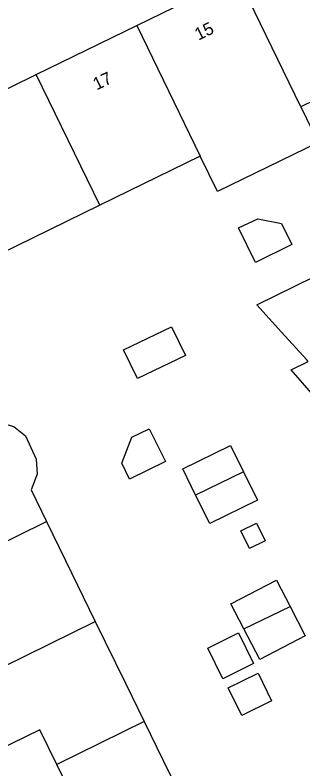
# Model space of a CAD drawing. Extents: x 160457 to 162082, y 388340 to 389736.
# Drawn here: x 160790 to 160813.2, y 388775.3 to 388835.9 of the extents above; entities that cross this region are included whole.
import ezdxf

# ---------------------------------------------------------------- set-up
doc = ezdxf.new("R2010")
doc.units = 0
doc.layers.add('IMGEO_Pand', color=7, linetype='Continuous')
doc.layers.add('IMGEO_Pand_nummerreeks', color=7, linetype='Continuous')

msp = doc.modelspace()

# ---------------------------------------------------------------- linework, layer by layer
at = {"layer": 'IMGEO_Pand'}
for points in [[(160807.926, 388838.972), (160816.305, 388843.064), (160816.478, 388842.742), (160816.37, 388842.689), (160821.325, 388832.529), (160813.027, 388828.476)], [(160799.832, 388835.019), (160807.926, 388838.972)], [(160813.027, 388828.476), (160807.926, 388838.972)], [(160791.746, 388831.069), (160799.832, 388835.019)], [(160799.832, 388835.019), (160804.945, 388824.528)], [(160783.66, 388827.12), (160791.746, 388831.069)], [(160796.865, 388820.581), (160791.746, 388831.069)], [(160813.027, 388828.476), (160814.416, 388825.619), (160806.337, 388821.673), (160804.945, 388824.528)], [(160804.945, 388824.528), (160796.865, 388820.581)], [(160796.865, 388820.581), (160788.782, 388816.633)], [(160809.381, 388815.983), (160808.031, 388818.746), (160809.564, 388819.495), (160811.484, 388819.096), (160812.307, 388817.412), (160809.381, 388815.983)], [(160813.637, 388808.009), (160813.488, 388808.173), (160811.49, 388810.37), (160809.493, 388812.567), (160814.137, 388814.839), (160818.628, 388817.036), (160821.252, 388811.672)], [(160799.882, 388806.648), (160798.774, 388808.962), (160802.639, 388810.812), (160803.746, 388808.498), (160799.882, 388806.648)], [(160816.137, 388802.883), (160815.992, 388803.05), (160814.791, 388804.429), (160812.251, 388807.343), (160813.637, 388808.009)], [(160777.041, 388797.369), (160776.904, 388797.662), (160781.436, 388799.775), (160786.382, 388802.287), (160788.669, 388803.147), (160789.935, 388802.8), (160790.875, 388802.036), (160791.746, 388800.169), (160791.808, 388798.959), (160791.328, 388797.695), (160792.571, 388795.154)], [(160799.261, 388798.561), (160798.632, 388799.84), (160799.447, 388801.927), (160800.842, 388802.614), (160802.14, 388799.977), (160799.261, 388798.561)], [(160804.57, 388797.282), (160803.528, 388799.399), (160807.372, 388801.279), (160808.422, 388799.147)], [(160808.422, 388799.147), (160804.57, 388797.282)], [(160808.422, 388799.147), (160809.543, 388796.872), (160805.699, 388794.992), (160804.57, 388797.282)], [(160782.547, 388790.23), (160785.541, 388791.701), (160792.571, 388795.154)], [(160792.571, 388795.154), (160794.101, 388792.028), (160796.497, 388787.131)], [(160808.207, 388794.418), (160809.479, 388795.039), (160810.173, 388793.62), (160808.901, 388792.999), (160808.207, 388794.418)], [(160808.457, 388786.533), (160807.413, 388788.546), (160811.079, 388790.447), (160812.178, 388788.328)], [(160812.178, 388788.328), (160813.391, 388785.988), (160809.725, 388784.087), (160808.457, 388786.533)], [(160808.457, 388786.533), (160812.178, 388788.328)], [(160785.414, 388781.697), (160796.497, 388787.131)], [(160796.497, 388787.131), (160798.923, 388782.173), (160800.43, 388779.094)], [(160805.55, 388784.997), (160808.025, 388786.208), (160809.232, 388783.742), (160806.757, 388782.531), (160805.55, 388784.997)], [(160807.197, 388781.797), (160809.602, 388782.974), (160810.683, 388780.765), (160808.278, 388779.588), (160807.197, 388781.797)], [(160793.401, 388775.643), (160792.029, 388778.429), (160787.408, 388776.179), (160785.583, 388779.926)], [(160800.43, 388779.094), (160793.401, 388775.643)], [(160800.43, 388779.094), (160801.966, 388775.955), (160804.365, 388771.054)], [(160791.989, 388766.839), (160790.163, 388770.583), (160794.784, 388772.835), (160793.401, 388775.643)]]:
    msp.add_lwpolyline(points, dxfattribs=at)

# ---------------------------------------------------------------- texts
at = {"layer": 'IMGEO_Pand_nummerreeks'}
for s, rotation, p in [('15', 26.02947, (160804.8, 388833.794)), ('17', 26.0313, (160796.612, 388829.794))]:
    msp.add_text(s, height=1, rotation=rotation, dxfattribs=at).set_placement(p)

doc.saveas('drawing.dxf')
